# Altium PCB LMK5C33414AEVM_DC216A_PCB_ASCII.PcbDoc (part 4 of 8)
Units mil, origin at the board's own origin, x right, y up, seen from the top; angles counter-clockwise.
Board outline 7000 x 9161 mil, 8 copper layers (L1-Top Layer (GTL), L2-GND Plane (GP1), L3-Mid-Layer 2 (G1), L4-Mid-Layer 3 (G2), L5-Mid-Layer 4 (G3), L6-Mid-Layer 5 (G4), L7-Mid-Layer 6 (G5), L8-Bottom Layer (GBL)), stack 61.2 mil thick; 523 components, 286 nets, 1391 pads, 2227 vias.
Unrouted connection lines stored in the file: 56.
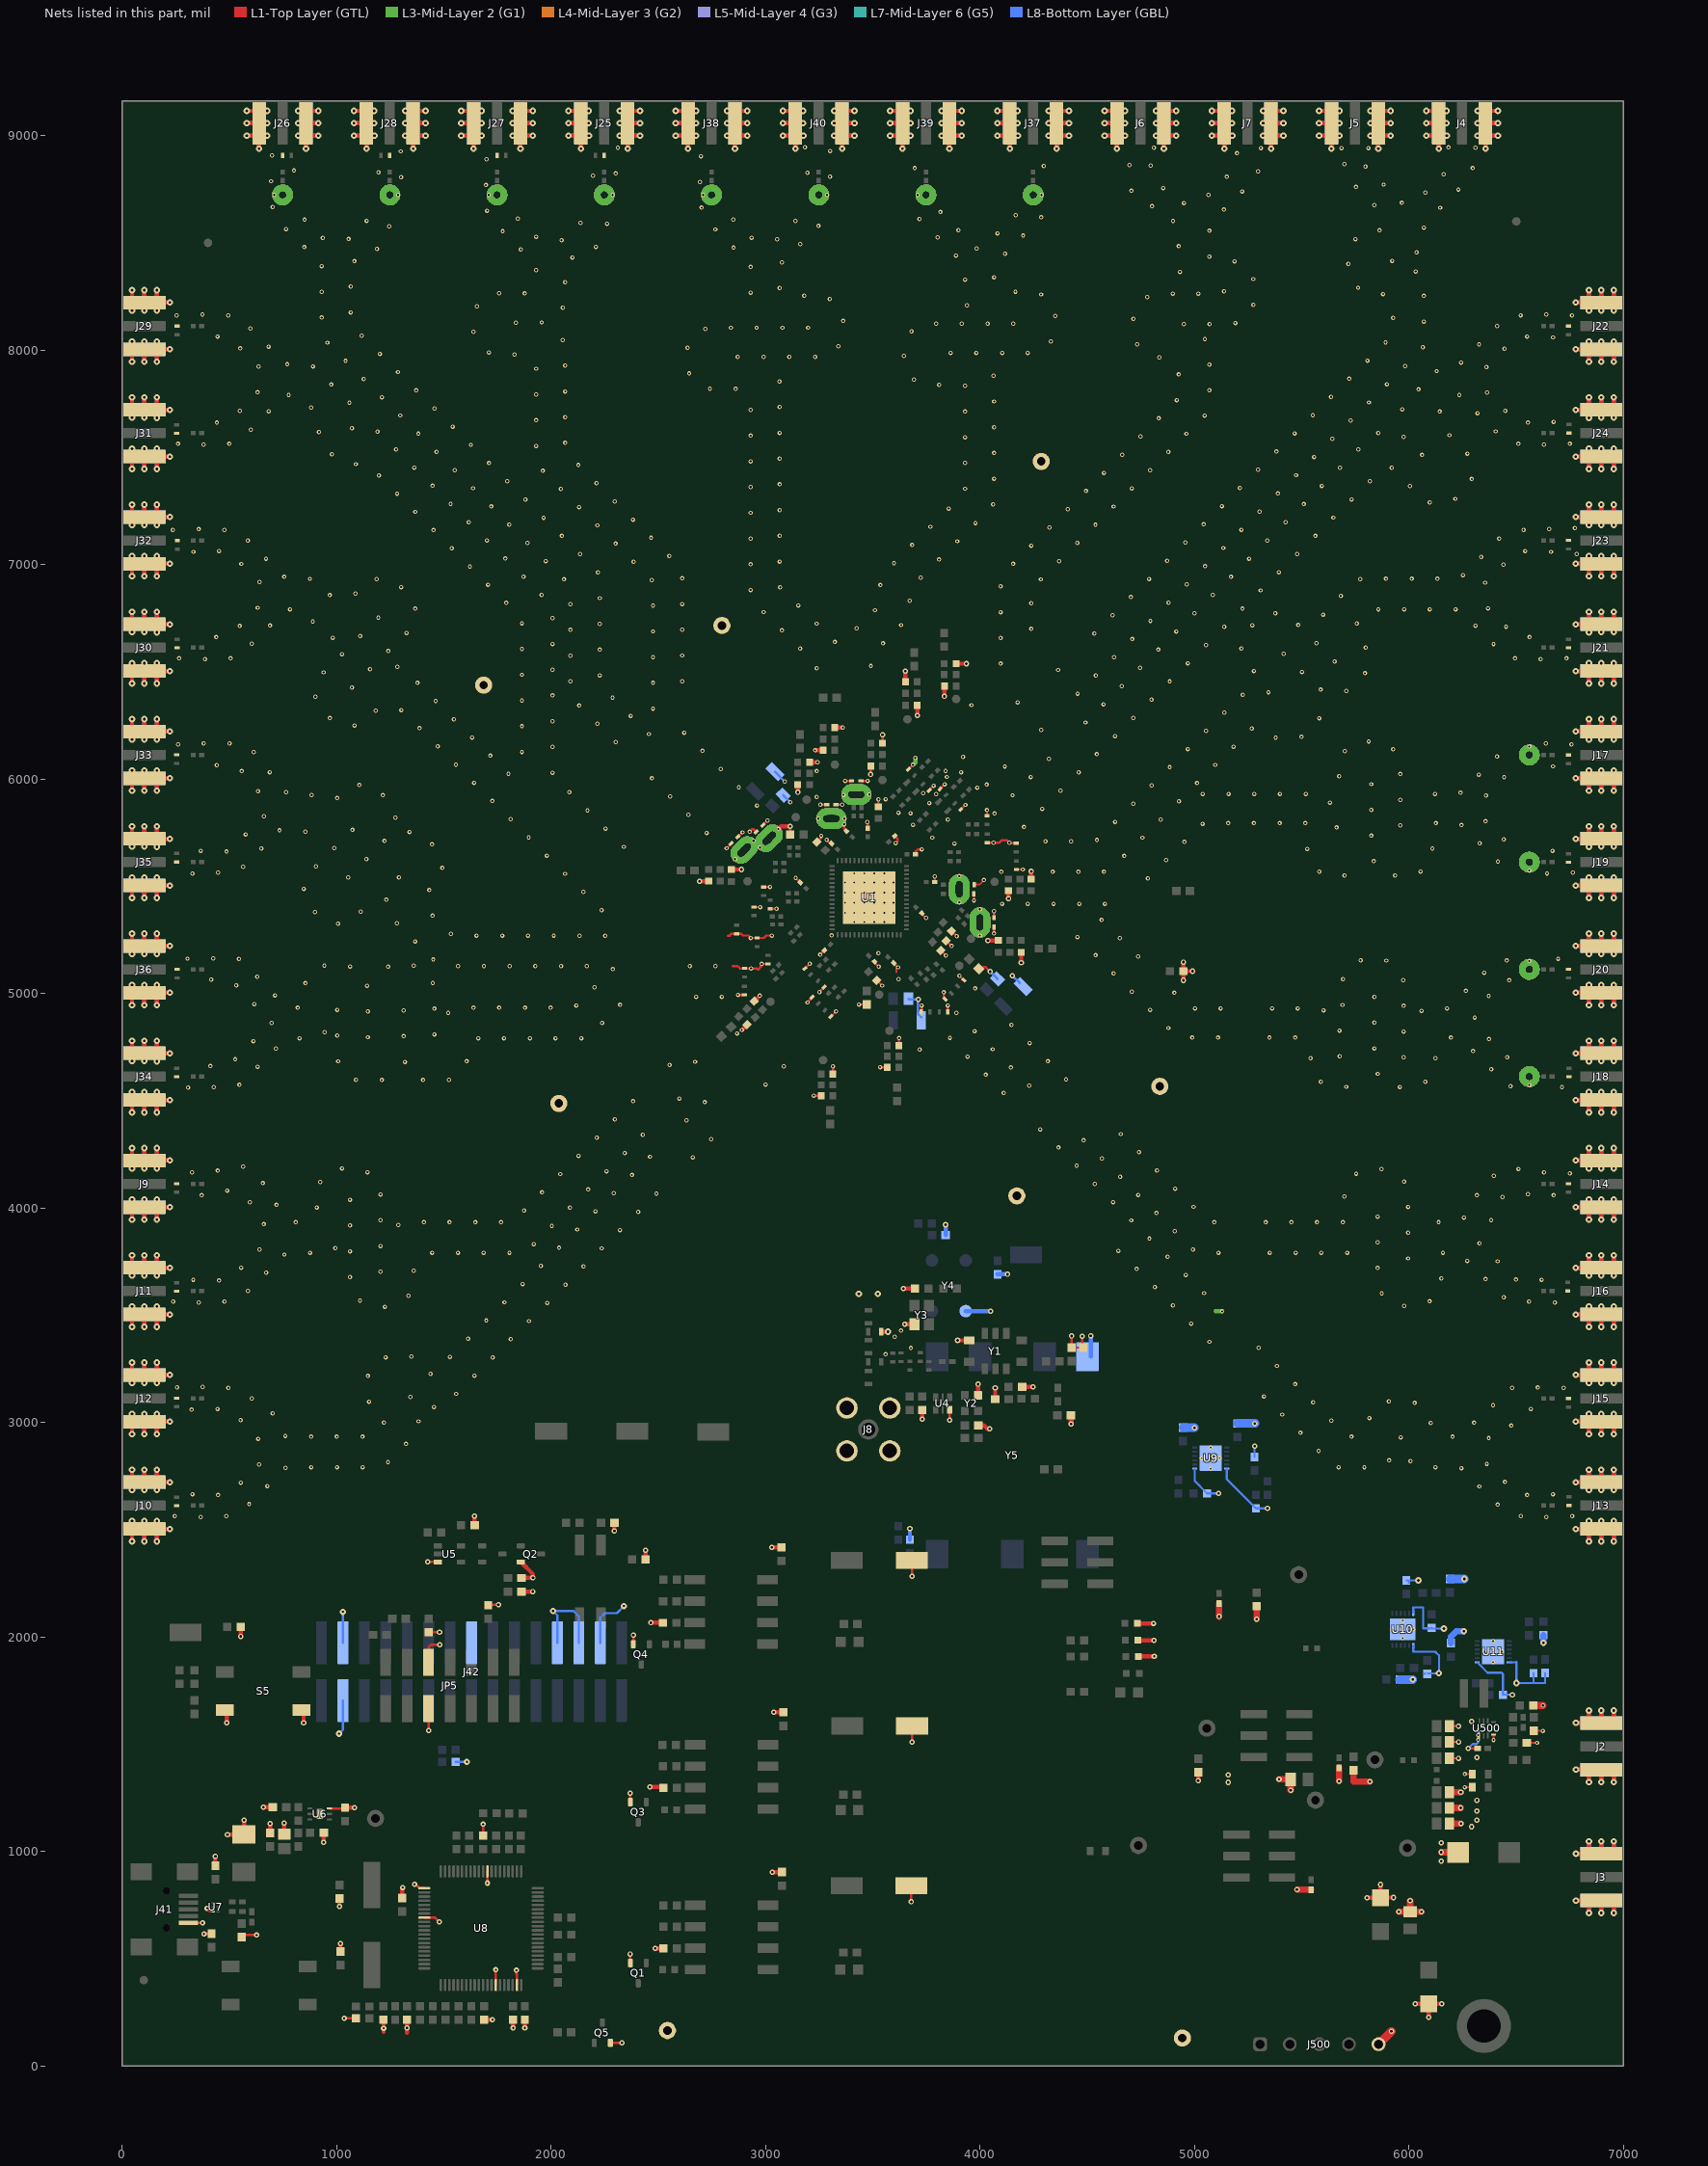
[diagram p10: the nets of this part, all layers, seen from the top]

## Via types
v1: diameter 20, hole 10, L1-Top Layer (GTL) to L8-Bottom Layer (GBL), tented top, 1246 vias
v2: diameter 30, hole 12, L1-Top Layer (GTL) to L8-Bottom Layer (GBL), 519 vias
v3: diameter 25, hole 12, L1-Top Layer (GTL) to L8-Bottom Layer (GBL), tented top, 198 vias
v4: diameter 30, hole 12, L1-Top Layer (GTL) to L8-Bottom Layer (GBL), tented top, 57 vias
v5: diameter 20, hole 10, L1-Top Layer (GTL) to L8-Bottom Layer (GBL), 47 vias
v6: diameter 19.68, hole 7.87, L1-Top Layer (GTL) to L8-Bottom Layer (GBL), 47 vias
v7: diameter 25, hole 10, L1-Top Layer (GTL) to L8-Bottom Layer (GBL), tented top, 35 vias
v8: diameter 25, hole 12, L1-Top Layer (GTL) to L8-Bottom Layer (GBL), 24 vias
v9: diameter 18, hole 10, L1-Top Layer (GTL) to L8-Bottom Layer (GBL), tented top, 12 vias
v10: diameter 40, hole 20, L1-Top Layer (GTL) to L8-Bottom Layer (GBL), 10 vias
v11: diameter 30, hole 10, L1-Top Layer (GTL) to L8-Bottom Layer (GBL), 10 vias
v12: diameter 39.37, hole 19.68, L1-Top Layer (GTL) to L8-Bottom Layer (GBL), tented top, 6 vias
v13: diameter 25, hole 10, L1-Top Layer (GTL) to L8-Bottom Layer (GBL), 5 vias
v14: diameter 23, hole 10, L1-Top Layer (GTL) to L8-Bottom Layer (GBL), tented top, 4 vias
v15: diameter 50, hole 28, L1-Top Layer (GTL) to L8-Bottom Layer (GBL), 4 vias
v16: diameter 20/0/0/0/0/0/20 (per signal layer), hole 10, L1-Top Layer (GTL) to L8-Bottom Layer (GBL), tented top, 2 vias
v17: diameter 25, hole 12, L1-Top Layer (GTL) to L8-Bottom Layer (GBL), tented both sides, 1 vias

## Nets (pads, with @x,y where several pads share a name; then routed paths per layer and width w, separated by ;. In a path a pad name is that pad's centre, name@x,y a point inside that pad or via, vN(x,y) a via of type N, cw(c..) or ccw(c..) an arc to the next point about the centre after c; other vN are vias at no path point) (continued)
GND: C1.2 C2.2 C6.1 C7.2 C8.2 C9.2 C10.2 C13.2 C21.1 C22.2 C23.2 C24.2 C27.2 C28.1 C29.2 C30.1 C31.1 C32.2 C33.1 C34.1 C35.2 C36.1 C37.1 C38.2 C39.1 C40.1 C41.2 C42.1 C43.1 C44.2 C45.1 C46.1 C47.2 C48.1 C49.1 C50.2 C51.1 C52.1 C53.2 C54.1 C55.1 C56.2 C57.1 C58.1 C59.2 C60.1 C61.2 C62.2 C63.2 C64.2 C65.2 C66.2 C67.2 C68.1 C69.2 C72.2 C73.1 C74.2 C75.2 C76.1 C77.2 C78.2 C79.1 C80.2 C81.2 C82.2 C83.2 C84.2 C85.2 C86.2 C87.2 C88.2 C89.1 C90.2 C91.2 C92.2 C93.2 C94.2 C95.2 C96.2 C97.2 C129.1 C130.2 C131.2 C132.1 C133.1 C134.1 C135.2 C136.2 C137.1 C138.1 C139.2 C140.1 C141.1 C142.1 C143.1 C144.1 C154.2 C155.2 C156.2 C500.2 C501.2 C502.2 C503.2 C504.2 C505.1 C506.1 C507.2 C508.2 C509.2 C510.2 C512.2 C513.2 C514.2 C515.2 C516.2 D1.2 D2.2 D3.2 D4.2 D5.2 D11.2 J2.2 J2.3 J2.4 J2.5 J3.2 J3.3 J3.4 J3.5 J4.2 J4.3 J4.4 J4.5 J5.2 J5.3 J5.4 J5.5 J6.2 J6.3 J6.4 J6.5 J7.2 J7.3 J7.4 J7.5 J8.2 J8.3 J8.4 J8.5 J9.2 J9.3 J9.4 J9.5 J10.2 J10.3 J10.4 J10.5 J11.2 J11.3 J11.4 J11.5 J12.2 J12.3 J12.4 J12.5 J13.2 J13.3 J13.4 J13.5 J14.2 J14.3 J14.4 J14.5 J15.2 J15.3 J15.4 J15.5 J16.2 J16.3 J16.4 J16.5 J17.2 J17.3 J17.4 J17.5 J18.2 J18.3 J18.4 J18.5 J19.2 J19.3 J19.4 J19.5 J20.2 J20.3 J20.4 J20.5 J21.2 J21.3 J21.4 J21.5 J22.2 J22.3 J22.4 J22.5 J23.2 J23.3 J23.4 J23.5 J24.2 J24.3 J24.4 J24.5 J25.2 J25.3 J25.4 J25.5 J26.2 J26.3 J26.4 J26.5 J27.2 J27.3 J27.4 J27.5 J28.2 J28.3 J28.4 J28.5 J29.2 J29.3 J29.4 J29.5 J30.2 J30.3 J30.4 J30.5 J31.2 J31.3 J31.4 J31.5 J32.2 J32.3 J32.4 J32.5 J33.2 J33.3 J33.4 J33.5 J34.2 J34.3 J34.4 J34.5 J35.2 J35.3 J35.4 J35.5 J36.2 J36.3 J36.4 J36.5 J37.2 J37.3 J37.4 J37.5 J38.2 J38.3 J38.4 J38.5 J39.2 J39.3 J39.4 J39.5 J40.2 J40.3 J40.4 J40.5 J41.5 J42.4 J42.6 J42.8 J42.16 J42.27 J42.28 J500.5 JP5.A03 JP5.B03 Q1.2 Q2.2 Q3.2 Q4.2 Q5.2 R2.1 R5.1 R9.1 R28.1 R32.1 R35.1 R39.1 R42.1 R45.2 R53.1 R62.1 R65.1 R69.1 R72.1 R78.2 R79.2 R82.2 R85.2 R86.2 R88.2 R90.2 R92.2 R94.2 R96.2 R99.2 R101.2 R103.2 R105.2 R109.2 R111.2 R113.2 R115.2 R117.2 R119.2 R121.2 R122.2 R125.2 R127.2 R129.2 R131.2 R133.2 R134.2 R135.2 R136.2 R138.2 R141.2 R143.2 R148.2 R149.1 R167.2 R168.2 R169.2 R170.2 R171.2 R172.2 R173.2 R174.2 R175.2 R176.2 R177.2 R178.2 R179.2 R180.2 R181.2 R182.2 R183.2 R184.2 R185.2 R186.2 R187.2 R188.2 R189.2 R190.2 R191.2 R204.2 R205.2 R502.1 R504.1 S5.3 S5.4 TP19.1 TP20.1 TP21.1 TP22.1 TP23.1 TP24.1 TP25.1 TP26.1 TP32.1 TP35.1 TP39.1 U1.65 U4.3 U5.3 U6.3 U6.7 U7.3 U8.14 U8.19 U8.49 U8.61 U8.68 U9.6 U9.7 U9.13 U10.6 U10.7 U10.13 U11.6 U11.7 U11.13 U500.4 U500.7 Y1.4 Y2.2 Y3.2 Y4.2 Y5.7 | length 95988.8
  L1-Top Layer (GTL) w10: v7(396,735) 396,730 405.68,720.32 U7.3@424.19,720.32 ; 2824,5269 2830.15,5269 ; 2833,5269 2830.15,5269 ; 2845.66,5127.3 2870.34,5127.3 2880.21,5117.43 ; R188.2@2944.73,5402.71 v1(2974.27,5402.71) ; v1(2981.18,5138) R191.2@3010.72,5138 ; R185.2@2991.21,5497 v1(3020.75,5497) ; R187.2@3021,5395 v1(3050.54,5395) ; v1(3029,5270) 3003,5270 2992,5259 R189.2@2960,5259 v1(2930.46,5259) 2919.46,5270 2894,5270 2886,5278 2839.15,5278 2830.15,5269 ; v1(3139.94,5538.93) C51.1@3161.14,5517.73 ; R167.2@3182.16,5116.54 3182.75,5116.54 3205.01,5138.8 v1(3205.6,5138.8) ; v1(3195.85,4958.13) 3195.85,4960.03 3216.56,4980.74 R170.2@3216.56,4982.64 ; C66.2@3239.25,5706.73 3259.02,5726.49 v1(3259.02,5735.31) ; v1(3250.5,5006.5) 3250.5,5007.11 3272.74,5029.35 R169.2@3272.74,5029.96 ; v1(3254.4,5181.04) C33.1@3274.58,5201.22 ; v1(3284.21,5716.79) C60.1@3304.25,5696.75 ; R168.2@3304.24,4893.56 3304.9,4893.56 3327.64,4916.3 v1(3328.3,4916.3) ; v1(3365.75,5789.01) 3365.75,5767.99 C57.1@3376.83,5756.91 ; v1(3435,4948.92) C67.2@3471.84,4948.92 ; v1(3474.04,5799.47) 3476.04,5797.47 C42.1@3476.04,5770.83 ; C48.1@3506.18,5146.28 v1(3527.04,5125.42) ; C62.2@3518.08,5061.96 v1(3543.34,5036.7) ; C39.1@3597.4,5142.27 v1@3616.66,5123.01 ; 3610,5101 3610,5114.35 v1(3617.66,5122.01) ; C54.1@3727,5373.31 3747.89,5352.42 v1(3747.89,5352.18) ; C45.1@3788.61,5519.89 v1(3788.61,5546.18) ; C65.2@3816.71,5201.07 v1(3840.61,5177.17) ; v3(3857.53,3011) U4.3@3857.53,3059.17 ; v1(3971.41,5434.16) R204.2@3971.41,5463.49 ; R176.2@3972,5508 3997,5508 v1(4018,5529) ; R178.2@4032,5829 v5(4032,5855) ; v1(4136.82,5702.51) 4138.64,5700.69 R205.2@4168,5700.69 ; R179.2@4169,5578.31 v1(4199.02,5578.31) ; C80.2@4426.24,3349.13 C80.2@4426.24,3349.38 ; v3(4426.24,3403.18) C80.2@4426.24,3349.38 ; C79.1@4475.99,3349.38 v3(4475.99,3402.56) ; C79.1@4480.99,3349.38 C80.2@4426.24,3349.38 ; C501.2@6185.33,1584.4 v8(6230.3,1584.4) ; C503.2@6188.03,1434.1 v8(6230.3,1434.1) ; C502.2@6188.03,1510.6 v8(6230.7,1510.6) ; v5(6259.4,1299.4) C506.1@6295.38,1299.4 ; v5(6259.8,1360.5) C505.1@6295.38,1360.5 ; v8@6276.5,1480.3 C507.2@6320.68,1480.3 ; v5(6322.1,1520.3) v5(6322.1,1542.3) ; v5(6393.92,1519.22) U500.7@6393.92,1544.47 ; C512.2@6549.1,1506.3 v5(6596.7,1506.3) ; R504.1@6581.9,1561.9 v5(6623.8,1561.9)
  L1-Top Layer (GTL) w11: 577.5,610 v7(626,610) ; U6.3@965.78,1200.18 1034.67,1200.18 C130.2@1039,1204.51 ; v7(1034.71,221.85) C139.2@1089.72,221.85 ; v3(1424.5,2349.5) U5.3@1471.28,2349.5 ; v3(1428.36,1563.6) JP5.A03@1428.36,1665.92 ; JP5.B03@1428.36,1880.88 1428.36,1952.36 1439,1963 v3(1480,1963) ; C92.2@1429.04,2022.18 v3(1479.28,2022.18) ; C93.2@1706,2150.43 v3(1753.79,2150.43) ; Q5.2@2275.8,107.08 v3(2329.92,107.08) ; Q1.2@2368.68,479.73 v3(2368.68,521.67) ; Q3.2@2368.69,1230.06 v3(2368.69,1272) ; Q4.2@2382.91,1966.04 v3(2382.91,2007.98) ; v1(2818.13,5677.07) R182.2@2839.69,5698.63 ; v1(2870.58,4993.86) R190.2@2901.07,4993.86 ; R184.2@2870.81,5729.74 v1(2892.37,5751.3) ; 2880.21,5117.43 R134.2@2901.71,5117.43 v1(2932.2,5117.43) 2958.89,5117.43 2964.64,5111.68 2981.18,5128.22 v1(2981.18,5138) ; v1(2924.96,5753.88) 2936.47,5765.4 2943.93,5765.4 R183.2@2955.45,5753.88 ; R181.2@2986.56,5785 v1(3008.12,5806.56) ; C75.2@3114.27,5741.54 v3(3114.27,5779.72) ; v1(3224.72,4524.1) C37.1@3258.53,4524.1 ; v1(3255.04,5880.05) R138.2@3284.39,5880.05 ; C38.2@3313.65,4623.46 v1(3313.65,4660.6) ; R143.2@3328.39,5880.2 v1(3356.88,5880.2) ; v1(3370.1,5991.63) R141.2@3400.59,5991.63 ; R136.2@3444.59,5991.63 v1(3475.08,5991.63) ; v3(3489.58,6021.24) C41.2@3489.58,6060.78 ; C61.2@3526.25,5871.25 v1(3526.25,5905.61) ; v1(3533.67,4656.73) C46.1@3566.8,4656.73 ; C40.1@3544.7,6166.96 v3(3544.7,6205.89) ; C36.1@3601.6,5734.83 3614.61,5721.82 3614.61,5709.51 v1(3606.81,5701.7) ; C47.2@3621.92,4756.58 v1(3621.92,4792.04) ; R35.1@3665.53,6044.9 v1(3687.09,6066.46) ; v3(3679,765) TP32.1@3679,840 ; v3(3682,2282) TP39.1@3682,2357 ; v3(3683,1510) TP35.1@3683,1585 ; C30.1@3699.03,5649.19 3699.03,5661.59 3709.24,5671.81 v1@3728.03,5671.81 ; R171.2@3727.02,4914.81 v1(3727.02,4944.19) ; R39.1@3761.75,5947.25 v1(3783.31,5968.81) ; R32.1@3813.05,5953.9 v1(3834.61,5975.46) ; v1(3830.4,5005.51) 3830.4,4979.46 R174.2@3836.8,4973.06 ; C64.2@3841.84,5246.38 v1(3866.95,5221.26) ; R173.2@3849.55,4914.64 v1(3849.55,4944.02) ; C63.2@3866.97,5291.68 v1(3891.19,5267.46) ; v1(3903.68,5082.9) R172.2@3924.05,5062.53 ; R28.1@3909.77,5857.94 v1(3931.33,5879.5) ; 4014.19,5123.38 4025.9,5123.38 v3(4047.22,5102.07) ; R180.2@4034,5703 v1(4063,5702.63) 4088.63,5702.63 4101,5715 4124.33,5715 v1(4136.82,5702.51) ; v1(4064.49,5279.75) R175.2@4064.49,5309.45 ; R177.2@4064.82,5353.81 v1(4064.82,5383.51)
  L1-Top Layer (GTL) w12: J41.5@308.36,667.01 v7(373.99,667.01) ; v7(381,615) 382.5,616.5 R148.2@416,616.5 ; v7@1367.71,846.85 1385.7,828.86 U8.61@1407.95,828.86 ; U8.68@1407.95,691.06 1458.5,691.06 v7(1477.71,671.85) ; C144.1@1682.71,1073.35 v7(1682.71,1126.85) ; U8.49@1702.24,906.61 v7(1702.24,852.32) v7@1702.71,851.85 ; U8.14@1741.61,377.09 v7@1741.61,448 ; v7(1838,446) 1838,426.56 1840.03,424.53 U8.19@1840.03,377.09
  L1-Top Layer (GTL) w20: v2(45.56,2445.57) J10.2@45.56,2503.44 ; v2@45.56,2542.7 J10.2@45.56,2503.44 ; v2@45.56,2682.3 J10.3@45.56,2721.56 ; v2(45.56,2779.43) J10.3@45.56,2721.56 ; v2(45.56,2945.57) J12.2@45.56,3003.44 ; v2@45.56,3042.7 J12.2@45.56,3003.44 ; v2@45.56,3182.3 J12.3@45.56,3221.56 ; v2(45.56,3279.43) J12.3@45.56,3221.56 ; v2(45.56,3445.57) J11.2@45.56,3503.44 ; v2@45.56,3542.7 J11.2@45.56,3503.44 ; v2@45.56,3682.3 J11.3@45.56,3721.56 ; v2(45.56,3779.43) J11.3@45.56,3721.56 ; v2(45.56,3945.57) J9.2@45.56,4003.44 ; v2@45.56,4042.7 J9.2@45.56,4003.44 ; v2@45.56,4182.3 J9.3@45.56,4221.56 ; v2(45.56,4279.43) J9.3@45.56,4221.56 ; v2(45.56,4445.57) J34.2@45.56,4503.44 ; v2@45.56,4542.7 J34.2@45.56,4503.44 ; v2@45.56,4682.3 J34.3@45.56,4721.56 ; v2(45.56,4779.43) J34.3@45.56,4721.56 ; v2(45.56,4945.57) J36.2@45.56,5003.44 ; v2@45.56,5042.7 J36.2@45.56,5003.44 ; v2@45.56,5182.3 J36.3@45.56,5221.56 ; v2(45.56,5279.43) J36.3@45.56,5221.56 ; v2(45.56,5445.57) J35.2@45.56,5503.44 ; v2@45.56,5542.7 J35.2@45.56,5503.44 ; v2@45.56,5682.3 J35.3@45.56,5721.56 ; v2(45.56,5779.43) J35.3@45.56,5721.56 ; v2(45.56,5945.57) J33.2@45.56,6003.44 ; v2@45.56,6042.7 J33.2@45.56,6003.44 ; v2@45.56,6182.3 J33.3@45.56,6221.56 ; v2(45.56,6279.43) J33.3@45.56,6221.56 ; v2(45.56,6445.57) J30.2@45.56,6503.44 ; v2@45.56,6542.7 J30.2@45.56,6503.44 ; v2@45.56,6682.3 J30.3@45.56,6721.56 ; v2(45.56,6779.43) J30.3@45.56,6721.56 ; v2(45.56,6945.57) J32.2@45.56,7003.44 ; v2@45.56,7042.7 J32.2@45.56,7003.44 ; v2@45.56,7182.3 J32.3@45.56,7221.56 ; v2(45.56,7279.43) J32.3@45.56,7221.56 ; v2(45.56,7445.57) J31.2@45.56,7503.44 ; v2@45.56,7542.7 J31.2@45.56,7503.44 ; v2@45.56,7682.3 J31.3@45.56,7721.56 ; v2(45.56,7779.43) J31.3@45.56,7721.56 ; v2(45.56,7945.57) J29.2@45.56,8003.44 ; v2@45.56,8042.7 J29.2@45.56,8003.44 ; v2@45.56,8182.3 J29.3@45.56,8221.56 ; v2(45.56,8279.43) J29.3@45.56,8221.56 ; v2(103.43,2445.57) J10.2@103.43,2503.44 ; v2@103.43,2542.7 J10.2@103.43,2503.44 ; v2@103.43,2682.3 J10.3@103.43,2721.56 ; v2(103.43,2779.43) J10.3@103.43,2721.56 ; v2(103.43,2945.57) J12.2@103.43,3003.44 ; v2@103.43,3042.7 J12.2@103.43,3003.44 ; v2@103.43,3182.3 J12.3@103.43,3221.56 ; v2(103.43,3279.43) J12.3@103.43,3221.56 ; v2(103.43,3445.57) J11.2@103.43,3503.44 ; v2@103.43,3542.7 J11.2@103.43,3503.44 ; v2@103.43,3682.3 J11.3@103.43,3721.56 ; v2(103.43,3779.43) J11.3@103.43,3721.56 ; v2(103.43,3945.57) J9.2@103.43,4003.44 ; v2@103.43,4042.7 J9.2@103.43,4003.44 ; v2@103.43,4182.3 J9.3@103.43,4221.56 ; v2(103.43,4279.43) J9.3@103.43,4221.56 ; v2(103.43,4445.57) J34.2@103.43,4503.44 ; v2@103.43,4542.7 J34.2@103.43,4503.44 ; v2@103.43,4682.3 J34.3@103.43,4721.56 ; v2(103.43,4779.43) J34.3@103.43,4721.56 ; v2(103.43,4945.57) J36.2@103.43,5003.44 ; v2@103.43,5042.7 J36.2@103.43,5003.44 ; v2@103.43,5182.3 J36.3@103.43,5221.56 ; v2(103.43,5279.43) J36.3@103.43,5221.56 ; v2(103.43,5445.57) J35.2@103.43,5503.44 ; v2@103.43,5542.7 J35.2@103.43,5503.44 ; v2@103.43,5682.3 J35.3@103.43,5721.56 ; v2(103.43,5779.43) J35.3@103.43,5721.56 ; v2(103.43,5945.57) J33.2@103.43,6003.44 ; v2@103.43,6042.7 J33.2@103.43,6003.44 ; v2@103.43,6182.3 J33.3@103.43,6221.56 ; v2(103.43,6279.43) J33.3@103.43,6221.56 ; v2(103.43,6445.57) J30.2@103.43,6503.44 ; v2@103.43,6542.7 J30.2@103.43,6503.44 ; v2@103.43,6682.3 J30.3@103.43,6721.56 ; v2(103.43,6779.43) J30.3@103.43,6721.56 ; v2(103.43,6945.57) J32.2@103.43,7003.44 ; v2@103.43,7042.7 J32.2@103.43,7003.44 ; v2@103.43,7182.3 J32.3@103.43,7221.56 ; v2(103.43,7279.43) J32.3@103.43,7221.56 ; v2(103.43,7445.57) J31.2@103.43,7503.44 ; v2@103.43,7542.7 J31.2@103.43,7503.44 ; v2@103.43,7682.3 J31.3@103.43,7721.56 ; v2(103.43,7779.43) J31.3@103.43,7721.56 ; v2(103.43,7945.57) J29.2@103.43,8003.44 ; v2@103.43,8042.7 J29.2@103.43,8003.44 ; v2@103.43,8182.3 J29.3@103.43,8221.56 ; v2(103.43,8279.43) J29.3@103.43,8221.56 ; v2@161,2543 161,2503.74 J10.2@161.3,2503.44 ; v2@161,2682 161,2721.26 J10.3@161.3,2721.56 ; v2@161,3043 161,3003.74 J12.2@161.3,3003.44 ; v2@161,3182 161,3221.26 J12.3@161.3,3221.56 ; v2@161,3543 161,3503.74 J11.2@161.3,3503.44 ; v2@161,3682 161,3721.26 J11.3@161.3,3721.56 ; v2@161,4043 161,4003.74 J9.2@161.3,4003.44 ; v2@161,4182 161,4221.26 J9.3@161.3,4221.56 ; v2@161,4543 161,4503.74 J34.2@161.3,4503.44 ; v2@161,4682 161,4721.26 J34.3@161.3,4721.56 ; v2@161,5043 161,5003.74 J36.2@161.3,5003.44 ; v2@161,5182 161,5221.26 J36.3@161.3,5221.56 ; v2@161,5543 161,5503.74 J35.2@161.3,5503.44 ; v2@161,5682 161,5721.26 J35.3@161.3,5721.56 ; v2@161,6043 161,6003.74 J33.2@161.3,6003.44 ; v2@161,6182 161,6221.26 J33.3@161.3,6221.56 ; v2@161,6543 161,6503.74 J30.2@161.3,6503.44 ; v2@161,6682 161,6721.26 J30.3@161.3,6721.56 ; v2@161,7043 161,7003.74 J32.2@161.3,7003.44 ; v2@161,7182 161,7221.26 J32.3@161.3,7221.56 ; v2@161,7543 161,7503.74 J31.2@161.3,7503.44 ; v2@161,7682 161,7721.26 J31.3@161.3,7721.56 ; v2@161,8043 161,8003.74 J29.2@161.3,8003.44 ; v2@161,8182 161,8221.26 J29.3@161.3,8221.56 ; v2(161.3,2445.57) J10.2@161.3,2503.44 ; v2(161.3,2779.43) J10.3@161.3,2721.56 ; v2(161.3,2945.57) J12.2@161.3,3003.44 ; v2(161.3,3279.43) J12.3@161.3,3221.56 ; v2(161.3,3445.57) J11.2@161.3,3503.44 ; v2(161.3,3779.43) J11.3@161.3,3721.56 ; v2(161.3,3945.57) J9.2@161.3,4003.44 ; v2(161.3,4279.43) J9.3@161.3,4221.56 ; v2(161.3,4445.57) J34.2@161.3,4503.44 ; v2(161.3,4779.43) J34.3@161.3,4721.56 ; v2(161.3,4945.57) J36.2@161.3,5003.44 ; v2(161.3,5279.43) J36.3@161.3,5221.56 ; v2(161.3,5445.57) J35.2@161.3,5503.44 ; v2(161.3,5779.43) J35.3@161.3,5721.56 ; v2(161.3,5945.57) J33.2@161.3,6003.44 ; v2(161.3,6279.43) J33.3@161.3,6221.56 ; v2(161.3,6445.57) J30.2@161.3,6503.44 ; v2(161.3,6779.43) J30.3@161.3,6721.56 ; v2(161.3,6945.57) J32.2@161.3,7003.44 ; v2(161.3,7279.43) J32.3@161.3,7221.56 ; v2(161.3,7445.57) J31.2@161.3,7503.44 ; v2(161.3,7779.43) J31.3@161.3,7721.56 ; v2(161.3,7945.57) J29.2@161.3,8003.44 ; v2(161.3,8279.43) J29.3@161.3,8221.56 ; J10.2@163.5,2503.44 v2(221.37,2503.44) ; J10.3@163.5,2721.56 v2(221.37,2721.56) ; J12.2@163.5,3003.44 v2(221.37,3003.44) ; J12.3@163.5,3221.56 v2(221.37,3221.56) ; J11.2@163.5,3503.44 v2(221.37,3503.44) ; J11.3@163.5,3721.56 v2(221.37,3721.56) ; J9.2@163.5,4003.44 v2(221.37,4003.44) ; J9.3@163.5,4221.56 v2(221.37,4221.56) ; J34.2@163.5,4503.44 v2(221.37,4503.44) ; J34.3@163.5,4721.56 v2(221.37,4721.56) ; J36.2@163.5,5003.44 v2(221.37,5003.44) ; J36.3@163.5,5221.56 v2(221.37,5221.56) ; J35.2@163.5,5503.44 v2(221.37,5503.44) ; J35.3@163.5,5721.56 v2(221.37,5721.56) ; J33.2@163.5,6003.44 v2(221.37,6003.44) ; J33.3@163.5,6221.56 v2(221.37,6221.56) ; J30.2@163.5,6503.44 v2(221.37,6503.44) ; J30.3@163.5,6721.56 v2(221.37,6721.56) ; J32.2@163.5,7003.44 v2(221.37,7003.44) ; J32.3@163.5,7221.56 v2(221.37,7221.56) ; J31.2@163.5,7503.44 v2(221.37,7503.44) ; J31.3@163.5,7721.56 v2(221.37,7721.56) ; J29.2@163.5,8003.44 v4(221.37,8003.44) ; J29.3@163.5,8221.56 v2(221.37,8221.56) ; C133.1@434.1,933.29 v3(434.1,977.79) ; S5.3@477.76,1659.56 487.29,1650.02 v3(487.29,1600.29) v3@487.29,1597.79 ; v3@486.89,1597.79 v3@486.89,1598.19 ; v3(490.66,1078.66) D11.2@567.86,1078.66 v3(567.86,1145.86) ; v3(552.66,2002.75) C96.2@552.66,2047.25 ; v2(580.57,8999.7) J26.2@638.44,8999.7 ; v2(580.57,9057.57) J26.2@638.44,9057.57 ; v2(580.57,9115.44) J26.2@638.44,9115.44 ; v2(638.44,8939.63) J26.2@638.44,8997.5 ; v3(657.75,1207) C132.1@701.5,1207 ; v2@677.7,9057.57 J26.2@638.44,9057.57 ; v2@677.7,9115.44 J26.2@638.44,9115.44 ; v2@678,9000 638.74,9000 J26.2@638.44,8999.7 ; C134.1@689.47,1085.72 v3(689.47,1129.47) ; C131.2@755.13,1079.94 v3(755.13,1131.87) ; v2@817,9000 856.26,9000 J26.3@856.56,8999.7 ; v2@817.3,9057.57 J26.3@856.56,9057.57 ; v2@817.3,9115.44 J26.3@856.56,9115.44 ; S5.4@836.02,1659.56 845.56,1650.02 845.56,1603.6 v3@848.47,1600.69 ; v2(856.56,8939.63) J26.3@856.56,8997.5 ; v2(914.43,8999.7) J26.3@856.56,8999.7 ; v2(914.43,9057.57) J26.3@856.56,9057.57 ; v2(914.43,9115.44) J26.3@856.56,9115.44 ; v3(939.46,1042.87) C129.1@939.46,1086.62 ; v7(1012.71,743) C135.2@1012.71,780.35 ; C136.2@1017.71,533.35 v7(1017.71,570.7) ; C130.2@1039,1204.51 v3(1082.75,1204.51) ; v2(1080.57,8999.7) J28.2@1138.44,8999.7 ; v2(1080.57,9057.57) J28.2@1138.44,9057.57 ; v2(1080.57,9115.44) J28.2@1138.44,9115.44 ; v2(1138.44,8939.63) J28.2@1138.44,8997.5 ; v2@1177.7,9057.57 J28.2@1138.44,9057.57 ; v2@1177.7,9115.44 J28.2@1138.44,9115.44 ; v2@1178,9000 1138.74,9000 J28.2@1138.44,8999.7 ; C137.1@1217.71,213.35 C137.1@1218.71,214.35 ; C137.1@1217.71,215.35 C137.1@1218.71,214.35 ; 1218.71,158 C137.1@1218.71,214.35 ; C140.1@1305.71,782.35 1305.71,829.85 v7(1307.71,831.85) ; v2@1317,9000 1356.26,9000 J28.3@1356.56,8999.7 ; v2@1317.3,9057.57 J28.3@1356.56,9057.57 ; v2@1317.3,9115.44 J28.3@1356.56,9115.44 ; C138.1@1326.71,214.35 C138.1@1327.71,215.35 1327.71,155 ; v2(1356.56,8939.63) J28.3@1356.56,8997.5 ; v2(1414.43,8999.7) J28.3@1356.56,8999.7 ; v2(1414.43,9057.57) J28.3@1356.56,9057.57 ; v2(1414.43,9115.44) J28.3@1356.56,9115.44 ; v2(1580.57,8999.7) J27.2@1638.44,8999.7 ; v2(1580.57,9057.57) J27.2@1638.44,9057.57 ; v2(1580.57,9115.44) J27.2@1638.44,9115.44 ; v2(1638.44,8939.63) J27.2@1638.44,8997.5 ; C89.1@1642.82,2520.22 v3(1642.82,2564.18) ; v2@1677.7,9057.57 J27.2@1638.44,9057.57 ; v2@1677.7,9115.44 J27.2@1638.44,9115.44 ; v2@1678,9000 1638.74,9000 J27.2@1638.44,8999.7 ; C142.1@1687.71,215.35 v7(1726.29,215.35) ; v2@1817,9000 1856.26,9000 J27.3@1856.56,8999.7 ; v2@1817.3,9057.57 J27.3@1856.56,9057.57 ; v2@1817.3,9115.44 J27.3@1856.56,9115.44 ; v7(1822.71,176.77) C143.1@1822.71,215.35 ; v2(1856.56,8939.63) J27.3@1856.56,8997.5 ; Q2.2@1858.17,2349.5 1915.05,2292.61 v3(1915.05,2276.57) 1862.4,2276.57 C90.2@1862.03,2276.2 ; R62.1@1862.03,2211.2 1862.4,2211.57 v3(1914.05,2211.56) ; v7(1877.05,176.77) C141.1@1877.05,215.35 ; v2(1914.43,8999.7) J27.3@1856.56,8999.7 ; v2(1914.43,9057.57) J27.3@1856.56,9057.57 ; v2(1914.43,9115.44) J27.3@1856.56,9115.44 ; v2(2080.57,8999.7) 2138.44,8999.7 J25.2@2138.44,9057.57 ; v2(2080.57,9057.57) J25.2@2138.44,9057.57 ; v2(2080.57,9115.44) J25.2@2138.44,9115.44 ; v2(2138.44,8939.63) J25.2@2138.44,8997.5 ; J25.2@2138.74,9000 v2@2178,9000 ; v2@2177.7,9057.57 J25.2@2138.44,9057.57 ; v2@2177.7,9115.44 J25.2@2138.44,9115.44 ; v3(2294.75,2493.21) R69.1@2294.75,2531.71 ; v2@2317,9000 2356.26,9000 J25.3@2356.56,8999.7 ; v2@2317.3,9057.57 J25.3@2356.56,9057.57 ; v2@2317.3,9115.44 J25.3@2356.56,9115.44 ; v2(2356.56,8939.63) J25.3@2356.56,8997.5 ; v2(2414.43,8999.7) J25.3@2356.56,8999.7 ; v2(2414.43,9057.57) J25.3@2356.56,9057.57 ; v2(2414.43,9115.44) J25.3@2356.56,9115.44 ; C94.2@2440.5,2361 v3(2440.5,2403.45) ; v3(2460.55,1300.6) 2517.99,1300.6 R65.1@2522.76,1295.82 ; v3(2464,2066) R72.1@2521.21,2066.05 ; v3(2485.01,548.55) R53.1@2523.52,548.55 ; v2(2580.57,8999.7) 2638.44,8999.7 J38.2@2638.44,9057.57 ; v2(2580.57,9057.57) J38.2@2638.44,9057.57 ; v2(2580.57,9115.44) J38.2@2638.44,9115.44 ; v2(2638.44,8939.63) J38.2@2638.44,8997.5 ; J38.2@2638.74,9000 v2@2678,9000 ; v2@2677.7,9057.57 J38.2@2638.44,9057.57 ; v2@2677.7,9115.44 J38.2@2638.44,9115.44 ; v3(2691.93,5523.49) C49.1@2734.38,5523.49 ; v2@2817,9000 2856.26,9000 J38.3@2856.56,8999.7 ; v2@2817.3,9057.57 J38.3@2856.56,9057.57 ; v2@2817.3,9115.44 J38.3@2856.56,9115.44 ; C50.2@2840.69,5578.3 v3(2887.76,5578.3) ; v2(2856.56,8939.63) J38.3@2856.56,8997.5 ; v1(2888.9,4830.02) C31.1@2913.03,4854.15 ; v2(2914.43,8999.7) J38.3@2856.56,8999.7 ; v2(2914.43,9057.57) J38.3@2856.56,9057.57 ; v2(2914.43,9115.44) J38.3@2856.56,9115.44 ; C32.2@2946.81,4963.91 v1(2972.59,4989.69) ; v3(3029.5,2417.5) C95.2@3074,2417.5 ; v3(3031.5,903.5) C88.2@3076,903.5 ; v3(3038.5,1648.5) C91.2@3083,1648.5 ; v1(3059.48,5767.23) 3071.97,5779.72 v3(3114.27,5779.72) ; v2(3080.57,8999.7) 3138.44,8999.7 J40.2@3138.44,9057.57 ; v2(3080.57,9057.57) J40.2@3138.44,9057.57 ; v2(3080.57,9115.44) J40.2@3138.44,9115.44 ; v2(3138.44,8939.63) J40.2@3138.44,8997.5 ; J40.2@3138.74,9000 v2@3178,9000 ; v3(3149.57,5938.03) C59.2@3149.57,5973.89 ; v2@3177.7,9057.57 J40.2@3138.44,9057.57 ; v2@3177.7,9115.44 J40.2@3138.44,9115.44 ; C58.1@3204.69,6077.89 v1(3241.92,6077.89) ; v1(3230.15,6133.77) C56.2@3267.38,6133.77 ; v2@3317,9000 3356.26,9000 J40.3@3356.56,8999.7 ; v2@3317.3,9057.57 J40.3@3356.56,9057.57 ; v2@3317.3,9115.44 J40.3@3356.56,9115.44 ; C55.1@3322.5,6239.95 v1(3359.73,6239.95) ; v2(3356.56,8939.63) J40.3@3356.56,8997.5 ; v2(3414.43,8999.7) J40.3@3356.56,8999.7 ; v2(3414.43,9057.57) J40.3@3356.56,9057.57 ; v2(3414.43,9115.44) J40.3@3356.56,9115.44 ; R42.1@3539,3423 v4(3570.1,3423) ; v2(3580.57,8999.7) 3638.44,8999.7 J39.2@3638.44,9057.57 ; v2(3580.57,9057.57) J39.2@3638.44,9057.57 ; v2(3580.57,9115.44) J39.2@3638.44,9115.44 ; v2(3638.44,8939.63) J39.2@3638.44,8997.5 ; J39.2@3638.74,9000 v2@3678,9000 ; v3(3642.84,3624.84) C83.2@3696.14,3624.84 ; v7(3648.46,3457.73) Y3.2@3693.86,3457.73 ; C34.1@3651,6453 v3(3651,6503.45) ; v2@3677.7,9057.57 J39.2@3638.44,9057.57 ; v2@3677.7,9115.44 J39.2@3638.44,9115.44 ; v3(3706.73,6295.69) C35.2@3706.73,6344.14 ; v3(3729.54,3015.46) C87.2@3729.54,3058.21 ; v2@3817,9000 3856.26,9000 J39.3@3856.56,8999.7 ; v2@3817.3,9057.57 J39.3@3856.56,9057.57 ; v2@3817.3,9115.44 J39.3@3856.56,9115.44 ; v3(3833.61,6385.22) C29.2@3833.61,6433.67 ; v2(3856.56,8939.63) J39.3@3856.56,8997.5 ; C28.1@3887.39,6537.74 v3(3935.84,6537.74) ; v3(3894.97,3382.66) Y1.4@3946.72,3382.66 ; v2(3914.43,8999.7) J39.3@3856.56,8999.7 ; v2(3914.43,9057.57) J39.3@3856.56,9057.57 ; v2(3914.43,9115.44) J39.3@3856.56,9115.44 ; Y2.2@3989.9,3126.73 v3(3989.9,3178.48) ; C82.2@3991.36,2985.56 4018.44,2985.56 4034,2970 v3(4045,2970) ; v3(4036.32,5247.23) C53.2@4084.77,5247.23 ; R45.2@4070.43,3108.93 v3(4070.43,3160.68) ; v2(4080.57,8999.7) 4138.44,8999.7 J37.2@4138.44,9057.57 ; v2(4080.57,9057.57) J37.2@4138.44,9057.57 ; v2(4080.57,9115.44) J37.2@4138.44,9115.44 ; v3(4133,5443.04) C44.2@4133,5478.47 ; v2(4138.44,8939.63) J37.2@4138.44,8997.5 ; J37.2@4138.74,9000 v2@4178,9000 ; v2@4177.7,9057.57 J37.2@4138.44,9057.57 ; v2@4177.7,9115.44 J37.2@4138.44,9115.44 ; v3(4191.67,5143.65) C52.1@4191.67,5192.11 ; C81.2@4195.69,3166.46 v3(4247.44,3166.46) ; C43.1@4238.63,5533.59 v3(4238.63,5569.45) ; v2@4317,9000 4356.26,9000 J37.3@4356.56,8999.7 ; v2@4317.3,9057.57 J37.3@4356.56,9057.57 ; v2@4317.3,9115.44 J37.3@4356.56,9115.44 ; v2(4356.56,8939.63) J37.3@4356.56,8997.5 ; v2(4414.43,8999.7) J37.3@4356.56,8999.7 ; v2(4414.43,9057.57) J37.3@4356.56,9057.57 ; v2(4414.43,9115.44) J37.3@4356.56,9115.44 ; v2(4580.57,8999.7) 4638.44,8999.7 J6.2@4638.44,9057.57 ; v2(4580.57,9057.57) J6.2@4638.44,9057.57 ; v2(4580.57,9115.44) J6.2@4638.44,9115.44 ; v2(4638.44,8939.63) J6.2@4638.44,8997.5 ; J6.2@4638.74,9000 v2@4678,9000 ; v2@4677.7,9057.57 J6.2@4638.44,9057.57 ; v2@4677.7,9115.44 J6.2@4638.44,9115.44 ; D5.2@4734.4,2062.98 v7(4808.79,2062.98) ; D3.2@4736.22,1983.98 v7(4810.61,1983.98) ; D4.2@4737.54,1909.24 v7(4811.93,1909.24) ; v2@4817,9000 4856.26,9000 J6.3@4856.56,8999.7 ; v2@4817.3,9057.57 J6.3@4856.56,9057.57 ; v2@4817.3,9115.44 J6.3@4856.56,9115.44 ; v2(4856.56,8939.63) J6.3@4856.56,8997.5 ; v2(4914.43,8999.7) J6.3@4856.56,8999.7 ; v2(4914.43,9057.57) J6.3@4856.56,9057.57 ; v2(4914.43,9115.44) J6.3@4856.56,9115.44 ; v3(4947.5,5061.5) C6.1@4947.5,5104 ; v3(4947.5,5146.5) C6.1@4947.5,5104 ; v3(4990,5104) C6.1@4947.5,5104 ; v3@5017.76,1338.08 C21.1@5017.76,1369.18 ; v2(5080.57,8999.7) 5138.44,8999.7 J7.2@5138.44,9057.57 ; v2(5080.57,9057.57) J7.2@5138.44,9057.57 ; v2(5080.57,9115.44) J7.2@5138.44,9115.44 ; v2(5138.44,8939.63) J7.2@5138.44,8997.5 ; J7.2@5138.74,9000 v2@5178,9000 ; v2@5177.7,9057.57 J7.2@5138.44,9057.57 ; v2@5177.7,9115.44 J7.2@5138.44,9115.44 ; v2@5317,9000 5356.26,9000 J7.3@5356.56,8999.7 ; v2@5317.3,9057.57 J7.3@5356.56,9057.57 ; v2@5317.3,9115.44 J7.3@5356.56,9115.44 ; v2(5356.56,8939.63) J7.3@5356.56,8997.5 ; v2(5414.43,8999.7) J7.3@5356.56,8999.7 ; v2(5414.43,9057.57) J7.3@5356.56,9057.57 ; v2(5414.43,9115.44) J7.3@5356.56,9115.44 ; v2(5580.57,8999.7) 5638.44,8999.7 J5.2@5638.44,9057.57 ; v2(5580.57,9057.57) J5.2@5638.44,9057.57 ; v2(5580.57,9115.44) J5.2@5638.44,9115.44 ; v2(5638.44,8939.63) J5.2@5638.44,8997.5 ; J5.2@5638.74,9000 v2@5678,9000 ; v8(5673.9,1327) v8@5673.9,1329.2 ; v2@5677.7,9057.57 J5.2@5638.44,9057.57 ; v2@5677.7,9115.44 J5.2@5638.44,9115.44 ; v3(5804.66,783.72) D1.2@5866.47,783.72 D1.2@5866.47,785 ; v2@5817,9000 5856.26,9000 J5.3@5856.56,8999.7 ; v2@5817.3,9057.57 J5.3@5856.56,9057.57 ; v2@5817.3,9115.44 J5.3@5856.56,9115.44 ; v2(5856.56,8939.63) J5.3@5856.56,8997.5 ; D1.2@5866,785 D1.2@5866.47,785 ; v3(5866.47,845.53) D1.2@5866.47,785 ; v2(5914.43,8999.7) J5.3@5856.56,8999.7 ; v2(5914.43,9057.57) J5.3@5856.56,9057.57 ; v2(5914.43,9115.44) J5.3@5856.56,9115.44 ; v3(5927.81,785) D1.2@5866.47,785 ; v3(6029.53,288.86) D2.2@6091.34,288.86 ; v2(6080.57,8999.7) 6138.44,8999.7 J4.2@6138.44,9057.57 ; v2(6080.57,9057.57) J4.2@6138.44,9057.57 ; v2(6080.57,9115.44) J4.2@6138.44,9115.44 ; v3(6091.34,227.05) D2.2@6091.34,288.86 ; v2(6138.44,8939.63) J4.2@6138.44,8997.5 ; J4.2@6138.74,9000 v2@6178,9000 ; v3(6153.15,288.86) D2.2@6091.34,288.86 ; v2@6177.7,9057.57 J4.2@6138.44,9057.57 ; v2@6177.7,9115.44 J4.2@6138.44,9115.44 ; v2@6317,9000 6356.26,9000 J4.3@6356.56,8999.7 ; v2@6317.3,9057.57 J4.3@6356.56,9057.57 ; v2@6317.3,9115.44 J4.3@6356.56,9115.44 ; v2(6356.56,8939.63) J4.3@6356.56,8997.5 ; v2(6414.43,8999.7) J4.3@6356.56,8999.7 ; v2(6414.43,9057.57) J4.3@6356.56,9057.57 ; v2(6414.43,9115.44) J4.3@6356.56,9115.44 ; v2(6777.83,2503.44) J13.3@6838.7,2503.44 ; v2(6777.83,2721.56) J13.2@6838.7,2721.56 ; v2(6777.83,3003.44) J15.3@6838.7,3003.44 ; v2(6777.83,3221.56) J15.2@6838.7,3221.56 ; v2(6777.83,3503.44) J16.3@6838.7,3503.44 ; v2(6777.83,3721.56) J16.2@6838.7,3721.56 ; v2(6777.83,4003.44) J14.3@6838.7,4003.44 ; v2(6777.83,4221.56) J14.2@6838.7,4221.56 ; v2(6777.83,4503.44) J18.3@6838.7,4503.44 ; v2(6777.83,4721.56) J18.2@6838.7,4721.56 ; v2(6777.83,5003.44) J20.3@6838.7,5003.44 ; v2(6777.83,5221.56) J20.2@6838.7,5221.56 ; v2(6777.83,5503.44) J19.3@6838.7,5503.44 ; v2(6777.83,5721.56) J19.2@6838.7,5721.56 ; v2(6777.83,6003.44) J17.3@6838.7,6003.44 ; v2(6777.83,6221.56) J17.2@6838.7,6221.56 ; v2(6777.83,6503.44) J21.3@6838.7,6503.44 ; v2(6777.83,6721.56) J21.2@6838.7,6721.56 ; v2(6777.83,7003.44) J23.3@6838.7,7003.44 ; v2(6777.83,7221.56) J23.2@6838.7,7221.56 ; v2(6777.83,7503.44) J24.3@6838.7,7503.44 ; v2(6777.83,7721.56) J24.2@6838.7,7721.56 ; v2(6777.83,8003.44) J22.3@6838.7,8003.44 ; v2(6777.83,8221.56) J22.2@6838.7,8221.56 ; v2(6778.63,770.94) J3.3@6836.5,770.94 ; v2(6778.63,989.06) J3.2@6836.5,989.06 ; v2(6778.63,1380.94) J2.3@6836.5,1380.94 ; v2(6778.63,1599.06) J2.2@6836.5,1599.06 ; v2(6838.7,713.07) 6838.7,770.94 J3.3@6896.57,770.94 ; v2(6838.7,1046.93) 6838.7,989.06 J3.2@6896.57,989.06 ; v2(6838.7,1323.07) 6838.7,1380.94 J2.3@6896.57,1380.94 ; v2(6838.7,1656.93) 6838.7,1599.06 J2.2@6896.57,1599.06 ; v2(6838.7,2445.57) J13.3@6838.7,2503.44 ; v2(6838.7,2779.43) J13.2@6838.7,2721.56 ; v2(6838.7,2945.57) J15.3@6838.7,3003.44 ; v2(6838.7,3279.43) J15.2@6838.7,3221.56 ; v2(6838.7,3445.57) J16.3@6838.7,3503.44 ; v2(6838.7,3779.43) J16.2@6838.7,3721.56 ; v2(6838.7,3945.57) J14.3@6838.7,4003.44 ; v2(6838.7,4279.43) J14.2@6838.7,4221.56 ; v2(6838.7,4445.57) J18.3@6838.7,4503.44 ; v2(6838.7,4779.43) J18.2@6838.7,4721.56 ; v2(6838.7,4945.57) J20.3@6838.7,5003.44 ; v2(6838.7,5279.43) J20.2@6838.7,5221.56 ; v2(6838.7,5445.57) J19.3@6838.7,5503.44 ; v2(6838.7,5779.43) J19.2@6838.7,5721.56 ; v2(6838.7,5945.57) J17.3@6838.7,6003.44 ; v2(6838.7,6279.43) J17.2@6838.7,6221.56 ; v2(6838.7,6445.57) J21.3@6838.7,6503.44 ; v2(6838.7,6779.43) J21.2@6838.7,6721.56 ; v2(6838.7,6945.57) J23.3@6838.7,7003.44 ; v2(6838.7,7279.43) J23.2@6838.7,7221.56 ; v2(6838.7,7445.57) J24.3@6838.7,7503.44 ; v2(6838.7,7779.43) J24.2@6838.7,7721.56 ; v2(6838.7,7945.57) J22.3@6838.7,8003.44 ; v2(6838.7,8279.43) J22.2@6838.7,8221.56 ; v2@6839,2543 6839,2503.74 J13.3@6838.7,2503.44 ; v2@6839,2682 6839,2721.26 J13.2@6838.7,2721.56 ; v2@6839,3043 6839,3003.74 J15.3@6838.7,3003.44 ; v2@6839,3182 6839,3221.26 J15.2@6838.7,3221.56 ; v2@6839,3543 6839,3503.74 J16.3@6838.7,3503.44 ; v2@6839,3682 6839,3721.26 J16.2@6838.7,3721.56 ; v2@6839,4043 6839,4003.74 J14.3@6838.7,4003.44 ; v2@6839,4182 6839,4221.26 J14.2@6838.7,4221.56 ; v2@6839,4543 6839,4503.74 J18.3@6838.7,4503.44 ; v2@6839,4682 6839,4721.26 J18.2@6838.7,4721.56 ; v2@6839,5043 6839,5003.74 J20.3@6838.7,5003.44 ; v2@6839,5182 6839,5221.26 J20.2@6838.7,5221.56 ; v2@6839,5543 6839,5503.74 J19.3@6838.7,5503.44 ; v2@6839,5682 6839,5721.26 J19.2@6838.7,5721.56 ; v2@6839,6043 6839,6003.74 J17.3@6838.7,6003.44 ; v2@6839,6182 6839,6221.26 J17.2@6838.7,6221.56 ; v2@6839,6543 6839,6503.74 J21.3@6838.7,6503.44 ; v2@6839,6682 6839,6721.26 J21.2@6838.7,6721.56 ; v2@6839,7043 6839,7003.74 J23.3@6838.7,7003.44 ; v2@6839,7182 6839,7221.26 J23.2@6838.7,7221.56 ; v2@6839,7543 6839,7503.74 J24.3@6838.7,7503.44 ; v2@6839,7682 6839,7721.26 J24.2@6838.7,7721.56 ; v2@6839,8043 6839,8003.74 J22.3@6838.7,8003.44 ; v2@6839,8182 6839,8221.26 J22.2@6838.7,8221.56 ; v2(6896.57,713.07) J3.3@6896.57,770.94 ; v2(6896.57,1046.93) J3.2@6896.57,989.06 ; v2(6896.57,1323.07) J2.3@6896.57,1380.94 ; v2(6896.57,1656.93) J2.2@6896.57,1599.06 ; v2(6896.57,2445.57) J13.3@6896.57,2503.44 ; v2@6896.57,2542.7 J13.3@6896.57,2503.44 ; v2@6896.57,2682.3 J13.2@6896.57,2721.56 ; v2(6896.57,2779.43) J13.2@6896.57,2721.56 ; v2(6896.57,2945.57) J15.3@6896.57,3003.44 ; v2@6896.57,3042.7 J15.3@6896.57,3003.44 ; v2@6896.57,3182.3 J15.2@6896.57,3221.56 ; v2(6896.57,3279.43) J15.2@6896.57,3221.56 ; v2(6896.57,3445.57) J16.3@6896.57,3503.44 ; v2@6896.57,3542.7 J16.3@6896.57,3503.44 ; v2@6896.57,3682.3 J16.2@6896.57,3721.56 ; v2(6896.57,3779.43) J16.2@6896.57,3721.56 ; v2(6896.57,3945.57) J14.3@6896.57,4003.44 ; v2@6896.57,4042.7 J14.3@6896.57,4003.44 ; v2@6896.57,4182.3 J14.2@6896.57,4221.56 ; v2(6896.57,4279.43) J14.2@6896.57,4221.56 ; v2(6896.57,4445.57) J18.3@6896.57,4503.44 ; v2@6896.57,4542.7 J18.3@6896.57,4503.44 ; v2@6896.57,4682.3 J18.2@6896.57,4721.56 ; v2(6896.57,4779.43) J18.2@6896.57,4721.56 ; v2(6896.57,4945.57) J20.3@6896.57,5003.44 ; v2@6896.57,5042.7 J20.3@6896.57,5003.44 ; v2@6896.57,5182.3 J20.2@6896.57,5221.56 ; v2(6896.57,5279.43) J20.2@6896.57,5221.56 ; v2(6896.57,5445.57) J19.3@6896.57,5503.44 ; v2@6896.57,5542.7 J19.3@6896.57,5503.44 ; v2@6896.57,5682.3 J19.2@6896.57,5721.56 ; v2(6896.57,5779.43) J19.2@6896.57,5721.56 ; v2(6896.57,5945.57) J17.3@6896.57,6003.44 ; v2@6896.57,6042.7 J17.3@6896.57,6003.44 ; v2@6896.57,6182.3 J17.2@6896.57,6221.56 ; v2(6896.57,6279.43) J17.2@6896.57,6221.56 ; v2(6896.57,6445.57) J21.3@6896.57,6503.44 ; v2@6896.57,6542.7 J21.3@6896.57,6503.44 ; v2@6896.57,6682.3 J21.2@6896.57,6721.56 ; v2(6896.57,6779.43) J21.2@6896.57,6721.56 ; v2(6896.57,6945.57) J23.3@6896.57,7003.44 ; v2@6896.57,7042.7 J23.3@6896.57,7003.44 ; v2@6896.57,7182.3 J23.2@6896.57,7221.56 ; v2(6896.57,7279.43) J23.2@6896.57,7221.56 ; v2(6896.57,7445.57) J24.3@6896.57,7503.44 ; v2@6896.57,7542.7 J24.3@6896.57,7503.44 ; v2@6896.57,7682.3 J24.2@6896.57,7721.56 ; v2(6896.57,7779.43) J24.2@6896.57,7721.56 ; v2(6896.57,7945.57) J22.3@6896.57,8003.44 ; v2@6896.57,8042.7 J22.3@6896.57,8003.44 ; v2@6896.57,8182.3 J22.2@6896.57,8221.56 ; v2(6896.57,8279.43) J22.2@6896.57,8221.56 ; v2(6954.44,713.07) 6954.44,770.94 J3.3@6896.57,770.94 ; v2(6954.44,1046.93) 6954.44,989.06 J3.2@6896.57,989.06 ; v2(6954.44,1323.07) 6954.44,1380.94 J2.3@6896.57,1380.94 ; v2(6954.44,1656.93) 6954.44,1599.06 J2.2@6896.57,1599.06 ; v2(6954.44,2445.57) J13.3@6954.44,2503.44 ; v2@6954.44,2542.7 J13.3@6954.44,2503.44 ; v2@6954.44,2682.3 J13.2@6954.44,2721.56 ; v2(6954.44,2779.43) J13.2@6954.44,2721.56 ; v2(6954.44,2945.57) J15.3@6954.44,3003.44 ; v2@6954.44,3042.7 J15.3@6954.44,3003.44 ; v2@6954.44,3182.3 J15.2@6954.44,3221.56 ; v2(6954.44,3279.43) J15.2@6954.44,3221.56 ; v2(6954.44,3445.57) J16.3@6954.44,3503.44 ; v2@6954.44,3542.7 J16.3@6954.44,3503.44 ; v2@6954.44,3682.3 J16.2@6954.44,3721.56 ; v2(6954.44,3779.43) J16.2@6954.44,3721.56 ; v2(6954.44,3945.57) J14.3@6954.44,4003.44 ; v2@6954.44,4042.7 J14.3@6954.44,4003.44 ; v2@6954.44,4182.3 J14.2@6954.44,4221.56 ; v2(6954.44,4279.43) J14.2@6954.44,4221.56 ; v2(6954.44,4445.57) J18.3@6954.44,4503.44 ; v2@6954.44,4542.7 J18.3@6954.44,4503.44 ; v2@6954.44,4682.3 J18.2@6954.44,4721.56 ; v2(6954.44,4779.43) J18.2@6954.44,4721.56 ; v2(6954.44,4945.57) J20.3@6954.44,5003.44 ; v2@6954.44,5042.7 J20.3@6954.44,5003.44 ; v2@6954.44,5182.3 J20.2@6954.44,5221.56 ; v2(6954.44,5279.43) J20.2@6954.44,5221.56 ; v2(6954.44,5445.57) J19.3@6954.44,5503.44 ; v2@6954.44,5542.7 J19.3@6954.44,5503.44 ; v2@6954.44,5682.3 J19.2@6954.44,5721.56 ; v2(6954.44,5779.43) J19.2@6954.44,5721.56 ; v2(6954.44,5945.57) J17.3@6954.44,6003.44 ; v2@6954.44,6042.7 J17.3@6954.44,6003.44 ; v2@6954.44,6182.3 J17.2@6954.44,6221.56 ; v2(6954.44,6279.43) J17.2@6954.44,6221.56 ; v2(6954.44,6445.57) J21.3@6954.44,6503.44 ; v2@6954.44,6542.7 J21.3@6954.44,6503.44 ; v2@6954.44,6682.3 J21.2@6954.44,6721.56 ; v2(6954.44,6779.43) J21.2@6954.44,6721.56 ; v2(6954.44,6945.57) J23.3@6954.44,7003.44 ; v2@6954.44,7042.7 J23.3@6954.44,7003.44 ; v2@6954.44,7182.3 J23.2@6954.44,7221.56 ; v2(6954.44,7279.43) J23.2@6954.44,7221.56 ; v2(6954.44,7445.57) J24.3@6954.44,7503.44 ; v2@6954.44,7542.7 J24.3@6954.44,7503.44 ; v2@6954.44,7682.3 J24.2@6954.44,7721.56 ; v2(6954.44,7779.43) J24.2@6954.44,7721.56 ; v2(6954.44,7945.57) J22.3@6954.44,8003.44 ; v2@6954.44,8042.7 J22.3@6954.44,8003.44 ; v2@6954.44,8182.3 J22.2@6954.44,8221.56 ; v2(6954.44,8279.43) J22.2@6954.44,8221.56 ; J10.2@45.56,2503.44 J10.2@103.43,2503.44 ; J10.3@45.56,2721.56 J10.3@103.43,2721.56 ; J12.2@45.56,3003.44 J12.2@103.43,3003.44 ; J12.3@45.56,3221.56 J12.3@103.43,3221.56 ; J11.2@45.56,3503.44 J11.2@103.43,3503.44 ; J11.3@45.56,3721.56 J11.3@103.43,3721.56 ; J9.2@45.56,4003.44 J9.2@103.43,4003.44 ; J9.3@45.56,4221.56 J9.3@103.43,4221.56 ; J34.2@45.56,4503.44 J34.2@103.43,4503.44 ; J34.3@45.56,4721.56 J34.3@103.43,4721.56 ; J36.2@45.56,5003.44 J36.2@103.43,5003.44 ; J36.3@45.56,5221.56 J36.3@103.43,5221.56 ; J35.2@45.56,5503.44 J35.2@103.43,5503.44 ; J35.3@45.56,5721.56 J35.3@103.43,5721.56 ; J33.2@45.56,6003.44 J33.2@103.43,6003.44 ; J33.3@45.56,6221.56 J33.3@103.43,6221.56 ; J30.2@45.56,6503.44 J30.2@103.43,6503.44 ; J30.3@45.56,6721.56 J30.3@103.43,6721.56 ; J32.2@45.56,7003.44 J32.2@103.43,7003.44 ; J32.3@45.56,7221.56 J32.3@103.43,7221.56 ; J31.2@45.56,7503.44 J31.2@103.43,7503.44 ; J31.3@45.56,7721.56 J31.3@103.43,7721.56 ; J29.2@45.56,8003.44 J29.2@103.43,8003.44 ; J29.3@45.56,8221.56 J29.3@103.43,8221.56 ; J10.2@103.43,2503.44 J10.2@161.3,2503.44 ; J10.3@103.43,2721.56 J10.3@161.3,2721.56 ; J12.2@103.43,3003.44 J12.2@161.3,3003.44 ; J12.3@103.43,3221.56 J12.3@161.3,3221.56 ; J11.2@103.43,3503.44 J11.2@161.3,3503.44 ; J11.3@103.43,3721.56 J11.3@161.3,3721.56 ; J9.2@103.43,4003.44 J9.2@161.3,4003.44 ; J9.3@103.43,4221.56 J9.3@161.3,4221.56 ; J34.2@103.43,4503.44 J34.2@161.3,4503.44 ; J34.3@103.43,4721.56 J34.3@161.3,4721.56 ; J36.2@103.43,5003.44 J36.2@161.3,5003.44 ; J36.3@103.43,5221.56 J36.3@161.3,5221.56 ; J35.2@103.43,5503.44 J35.2@161.3,5503.44 ; J35.3@103.43,5721.56 J35.3@161.3,5721.56 ; J33.2@103.43,6003.44 J33.2@161.3,6003.44 ; J33.3@103.43,6221.56 J33.3@161.3,6221.56 ; J30.2@103.43,6503.44 J30.2@161.3,6503.44 ; J30.3@103.43,6721.56 J30.3@161.3,6721.56 ; J32.2@103.43,7003.44 J32.2@161.3,7003.44 ; J32.3@103.43,7221.56 J32.3@161.3,7221.56 ; J31.2@103.43,7503.44 J31.2@161.3,7503.44 ; J31.3@103.43,7721.56 J31.3@161.3,7721.56 ; J29.2@103.43,8003.44 J29.2@161.3,8003.44 ; J29.3@103.43,8221.56 J29.3@161.3,8221.56 ; J26.2@638.44,8999.7 J26.2@638.44,9057.57 ; J26.2@638.44,9057.57 J26.2@638.44,9115.44 ; J26.3@856.56,8999.7 J26.3@856.56,9057.57 ; J26.3@856.56,9057.57 J26.3@856.56,9115.44 ; J28.2@1138.44,8999.7 J28.2@1138.44,9057.57 ; J28.2@1138.44,9057.57 J28.2@1138.44,9115.44 ; J28.3@1356.56,8999.7 J28.3@1356.56,9057.57 ; J28.3@1356.56,9057.57 J28.3@1356.56,9115.44 ; J27.2@1638.44,8999.7 J27.2@1638.44,9057.57 ; J27.2@1638.44,9057.57 J27.2@1638.44,9115.44 ; J27.3@1856.56,8999.7 J27.3@1856.56,9057.57 ; J27.3@1856.56,9057.57 J27.3@1856.56,9115.44 ; J25.2@2138.44,9057.57 J25.2@2138.44,9115.44 ; J25.3@2356.56,8999.7 J25.3@2356.56,9057.57 ; J25.3@2356.56,9057.57 J25.3@2356.56,9115.44 ; J38.2@2638.44,9057.57 J38.2@2638.44,9115.44 ; J38.3@2856.56,8999.7 J38.3@2856.56,9057.57 ; J38.3@2856.56,9057.57 J38.3@2856.56,9115.44 ; J40.2@3138.44,9057.57 J40.2@3138.44,9115.44 ; J40.3@3356.56,8999.7 J40.3@3356.56,9057.57 ; J40.3@3356.56,9057.57 J40.3@3356.56,9115.44 ; J39.2@3638.44,9057.57 J39.2@3638.44,9115.44 ; J39.3@3856.56,8999.7 J39.3@3856.56,9057.57 ; J39.3@3856.56,9057.57 J39.3@3856.56,9115.44 ; J37.2@4138.44,9057.57 J37.2@4138.44,9115.44 ; J37.3@4356.56,8999.7 J37.3@4356.56,9057.57 ; J37.3@4356.56,9057.57 J37.3@4356.56,9115.44 ; J6.2@4638.44,9057.57 J6.2@4638.44,9115.44 ; J6.3@4856.56,8999.7 J6.3@4856.56,9057.57 ; J6.3@4856.56,9057.57 J6.3@4856.56,9115.44 ; J7.2@5138.44,9057.57 J7.2@5138.44,9115.44 ; J7.3@5356.56,8999.7 J7.3@5356.56,9057.57 ; J7.3@5356.56,9057.57 J7.3@5356.56,9115.44 ; J5.2@5638.44,9057.57 J5.2@5638.44,9115.44 ; J5.3@5856.56,8999.7 J5.3@5856.56,9057.57 ; J5.3@5856.56,9057.57 J5.3@5856.56,9115.44 ; J4.2@6138.44,9057.57 J4.2@6138.44,9115.44 ; J4.3@6356.56,8999.7 J4.3@6356.56,9057.57 ; J4.3@6356.56,9057.57 J4.3@6356.56,9115.44 ; J13.3@6838.7,2503.44 J13.3@6896.57,2503.44 ; J13.2@6838.7,2721.56 J13.2@6896.57,2721.56 ; J15.3@6838.7,3003.44 J15.3@6896.57,3003.44 ; J15.2@6838.7,3221.56 J15.2@6896.57,3221.56 ; J16.3@6838.7,3503.44 J16.3@6896.57,3503.44 ; J16.2@6838.7,3721.56 J16.2@6896.57,3721.56 ; J14.3@6838.7,4003.44 J14.3@6896.57,4003.44 ; J14.2@6838.7,4221.56 J14.2@6896.57,4221.56 ; J18.3@6838.7,4503.44 J18.3@6896.57,4503.44 ; J18.2@6838.7,4721.56 J18.2@6896.57,4721.56 ; J20.3@6838.7,5003.44 J20.3@6896.57,5003.44 ; J20.2@6838.7,5221.56 J20.2@6896.57,5221.56 ; J19.3@6838.7,5503.44 J19.3@6896.57,5503.44 ; J19.2@6838.7,5721.56 J19.2@6896.57,5721.56 ; J17.3@6838.7,6003.44 J17.3@6896.57,6003.44 ; J17.2@6838.7,6221.56 J17.2@6896.57,6221.56 ; J21.3@6838.7,6503.44 J21.3@6896.57,6503.44 ; J21.2@6838.7,6721.56 J21.2@6896.57,6721.56 ; J23.3@6838.7,7003.44 J23.3@6896.57,7003.44 ; J23.2@6838.7,7221.56 J23.2@6896.57,7221.56 ; J24.3@6838.7,7503.44 J24.3@6896.57,7503.44 ; J24.2@6838.7,7721.56 J24.2@6896.57,7721.56 ; J22.3@6838.7,8003.44 J22.3@6896.57,8003.44 ; J22.2@6838.7,8221.56 J22.2@6896.57,8221.56 ; J13.3@6896.57,2503.44 J13.3@6954.44,2503.44 ; J13.2@6896.57,2721.56 J13.2@6954.44,2721.56 ; J15.3@6896.57,3003.44 J15.3@6954.44,3003.44 ; J15.2@6896.57,3221.56 J15.2@6954.44,3221.56 ; J16.3@6896.57,3503.44 J16.3@6954.44,3503.44 ; J16.2@6896.57,3721.56 J16.2@6954.44,3721.56 ; J14.3@6896.57,4003.44 J14.3@6954.44,4003.44 ; J14.2@6896.57,4221.56 J14.2@6954.44,4221.56 ; J18.3@6896.57,4503.44 J18.3@6954.44,4503.44 ; J18.2@6896.57,4721.56 J18.2@6954.44,4721.56 ; J20.3@6896.57,5003.44 J20.3@6954.44,5003.44 ; J20.2@6896.57,5221.56 J20.2@6954.44,5221.56 ; J19.3@6896.57,5503.44 J19.3@6954.44,5503.44 ; J19.2@6896.57,5721.56 J19.2@6954.44,5721.56 ; J17.3@6896.57,6003.44 J17.3@6954.44,6003.44 ; J17.2@6896.57,6221.56 J17.2@6954.44,6221.56 ; J21.3@6896.57,6503.44 J21.3@6954.44,6503.44 ; J21.2@6896.57,6721.56 J21.2@6954.44,6721.56 ; J23.3@6896.57,7003.44 J23.3@6954.44,7003.44 ; J23.2@6896.57,7221.56 J23.2@6954.44,7221.56 ; J24.3@6896.57,7503.44 J24.3@6954.44,7503.44 ; J24.2@6896.57,7721.56 J24.2@6954.44,7721.56 ; J22.3@6896.57,8003.44 J22.3@6954.44,8003.44 ; J22.2@6896.57,8221.56 J22.2@6954.44,8221.56
  L1-Top Layer (GTL) w25: v3(4423.76,2992.57) C78.2@4423.76,3032.57
  L1-Top Layer (GTL) w30: v8(5114.2,2095.3) C516.2@5114.2,2156.28 ; v8(5289.4,2082.4) C515.2@5289.4,2143.2 ; v7(5394.02,1336.34) C27.2@5448.12,1336.34 v3(5448.12,1284.22) ; v8@5477.88,821.78 C504.2@5543.6,821.78 ; v8(5673.9,1327) C514.2@5673.9,1389.48 ; C513.2@5740.8,1378.6 5740.8,1324.8 v8(5817,1324.8) ; v3(5953.08,718.49) C10.2@6005.2,718.49 ; v3(6005.2,770.61) C10.2@6005.2,718.49 ; v3(6057.32,718.49) C10.2@6005.2,718.49 ; v8(6150.2,996.3) C500.2@6228.51,995.9 ; C510.2@6188.03,1130 v8(6241.6,1130) ; C509.2@6188.03,1202.9 v8(6240.9,1202.9) ; C508.2@6188.03,1276.1 v8(6241.2,1276.1)
  L1-Top Layer (GTL) w35: R502.1@6579.5,1680.8 v5(6623.9,1680.8)
  L1-Top Layer (GTL) w40: J500.5@5857.7,101.2 v8(5917.9,161.4)
  L3-Mid-Layer 2 (G1) w20: v1(3687.09,6066.46) 3697.6,6076.97 v1(3697.6,6098.64) ; 5097.28,3518.08 v1(5128.91,3518.08)
  L3-Mid-Layer 2 (G1) w30: 780.5,8723.67 ccw(c747.5,8723.67) 780.5,8723.67 ; v5@1280.5,8723.67 ccw(c1247.5,8723.67) v5@1280.5,8723.67 ; 1780.5,8723.67 ccw(c1747.5,8723.67) 1780.5,8723.67 ; v5@2280.5,8723.67 ccw(c2247.5,8723.67) v5@2280.5,8723.67 ; 2780.5,8723.67 ccw(c2747.5,8723.67) 2780.5,8723.67 ; 2861.3,5677.02 ccw(c2884.64,5653.69) 2907.97,5630.35 2939.08,5661.47 ccw(c2915.75,5684.8) 2892.42,5708.13 2861.3,5677.02 ; 2977.46,5731.87 ccw(c3000.79,5708.54) 3024.12,5685.21 3055.24,5716.32 ccw(c3031.9,5739.65) 3008.57,5762.99 2977.46,5731.87 ; v5@3280.5,8723.67 ccw(c3247.5,8723.67) v5@3280.5,8723.67 ; 3284.39,5782.49 cw(c3284.39,5815.49) 3284.39,5848.49 3328.39,5848.49 cw(c3328.39,5815.49) 3328.39,5782.49 3284.39,5782.49 ; 3400.59,5894.67 cw(c3400.59,5927.67) 3400.59,5960.67 3444.59,5960.67 cw(c3444.59,5927.67) 3444.59,5894.67 3400.59,5894.67 ; 3780.5,8723.67 ccw(c3747.5,8723.67) 3780.5,8723.67 ; 3869.84,5464.22 ccw(c3902.84,5464.22) 3935.84,5464.22 3935.84,5508.22 ccw(c3902.84,5508.22) 3869.84,5508.22 3869.84,5464.22 ; 3965.89,5309.45 ccw(c3998.89,5309.45) 4031.89,5309.45 4031.89,5353.45 ccw(c3998.89,5353.45) 3965.89,5353.45 3965.89,5309.45 ; v5@4280.5,8723.67 ccw(c4247.5,8723.67) v5@4280.5,8723.67 ; 6593.67,4612.5 ccw(c6560.67,4612.5) 6593.67,4612.5 ; 6593.67,5112.5 ccw(c6560.67,5112.5) 6593.67,5112.5 ; 6593.67,5612.5 ccw(c6560.67,5612.5) 6593.67,5612.5 ; 6593.67,6112.5 ccw(c6560.67,6112.5) 6593.67,6112.5
  L4-Mid-Layer 3 (G2) w30: 780.5,8723.67 ccw(c747.5,8723.67) 780.5,8723.67 ; v5@1280.5,8723.67 ccw(c1247.5,8723.67) v5@1280.5,8723.67 ; 1780.5,8723.67 ccw(c1747.5,8723.67) 1780.5,8723.67 ; v5@2280.5,8723.67 ccw(c2247.5,8723.67) v5@2280.5,8723.67 ; 2780.5,8723.67 ccw(c2747.5,8723.67) 2780.5,8723.67 ; 2861.3,5677.02 ccw(c2884.64,5653.69) 2907.97,5630.35 2939.08,5661.46 ccw(c2915.75,5684.8) 2892.42,5708.13 2861.3,5677.02 ; 2977.45,5731.87 ccw(c3000.79,5708.54) 3024.12,5685.2 3055.24,5716.32 ccw(c3031.9,5739.65) 3008.57,5762.99 2977.45,5731.87 ; v5@3280.5,8723.67 ccw(c3247.5,8723.67) v5@3280.5,8723.67 ; 3284.39,5782.49 cw(c3284.39,5815.49) 3284.39,5848.49 3328.39,5848.49 cw(c3328.39,5815.49) 3328.39,5782.49 3284.39,5782.49 ; 3400.59,5894.67 cw(c3400.59,5927.67) 3400.59,5960.67 3444.59,5960.67 cw(c3444.59,5927.67) 3444.59,5894.67 3400.59,5894.67 ; 3780.5,8723.67 ccw(c3747.5,8723.67) 3780.5,8723.67 ; 3869.84,5464.22 ccw(c3902.84,5464.22) 3935.84,5464.22 3935.84,5508.22 ccw(c3902.84,5508.22) 3869.84,5508.22 3869.84,5464.22 ; 3965.89,5309.45 ccw(c3998.89,5309.45) 4031.89,5309.45 4031.89,5353.45 ccw(c3998.89,5353.45) 3965.89,5353.45 3965.89,5309.45 ; v5@4280.5,8723.67 ccw(c4247.5,8723.67) v5@4280.5,8723.67 ; 6593.67,4612.5 ccw(c6560.67,4612.5) 6593.67,4612.5 ; 6593.67,5112.5 ccw(c6560.67,5112.5) 6593.67,5112.5 ; 6593.67,5612.5 ccw(c6560.67,5612.5) 6593.67,5612.5 ; 6593.67,6112.5 ccw(c6560.67,6112.5) 6593.67,6112.5
  L5-Mid-Layer 4 (G3) w30: 780.5,8723.67 ccw(c747.5,8723.67) 780.5,8723.67 ; v5@1280.5,8723.67 ccw(c1247.5,8723.67) v5@1280.5,8723.67 ; 1780.5,8723.67 ccw(c1747.5,8723.67) 1780.5,8723.67 ; v5@2280.5,8723.67 ccw(c2247.5,8723.67) v5@2280.5,8723.67 ; 2780.5,8723.67 ccw(c2747.5,8723.67) 2780.5,8723.67 ; 2861.3,5677.02 ccw(c2884.64,5653.69) 2907.97,5630.35 2939.08,5661.47 ccw(c2915.75,5684.8) 2892.42,5708.13 2861.3,5677.02 ; 2977.46,5731.87 ccw(c3000.79,5708.54) 3024.12,5685.21 3055.24,5716.32 ccw(c3031.9,5739.65) 3008.57,5762.99 2977.46,5731.87 ; v5@3280.5,8723.67 ccw(c3247.5,8723.67) v5@3280.5,8723.67 ; 3284.39,5782.49 cw(c3284.39,5815.49) 3284.39,5848.49 3328.39,5848.49 cw(c3328.39,5815.49) 3328.39,5782.49 3284.39,5782.49 ; 3400.59,5894.67 cw(c3400.59,5927.67) 3400.59,5960.67 3444.59,5960.67 cw(c3444.59,5927.67) 3444.59,5894.67 3400.59,5894.67 ; 3780.5,8723.67 ccw(c3747.5,8723.67) 3780.5,8723.67 ; 3869.84,5464.22 ccw(c3902.84,5464.22) 3935.84,5464.22 3935.84,5508.22 ccw(c3902.84,5508.22) 3869.84,5508.22 3869.84,5464.22 ; 3965.89,5309.45 ccw(c3998.89,5309.45) 4031.89,5309.45 4031.89,5353.45 ccw(c3998.89,5353.45) 3965.89,5353.45 3965.89,5309.45 ; v5@4280.5,8723.67 ccw(c4247.5,8723.67) v5@4280.5,8723.67 ; 6593.67,4612.5 ccw(c6560.67,4612.5) 6593.67,4612.5 ; 6593.67,5112.5 ccw(c6560.67,5112.5) 6593.67,5112.5 ; 6593.67,5612.5 ccw(c6560.67,5612.5) 6593.67,5612.5 ; 6593.67,6112.5 ccw(c6560.67,6112.5) 6593.67,6112.5
  L7-Mid-Layer 6 (G5) w30: 780.5,8723.67 ccw(c747.5,8723.67) 780.5,8723.67 ; v5@1280.5,8723.67 ccw(c1247.5,8723.67) v5@1280.5,8723.67 ; 1780.5,8723.67 ccw(c1747.5,8723.67) 1780.5,8723.67 ; v5@2280.5,8723.67 ccw(c2247.5,8723.67) v5@2280.5,8723.67 ; 2780.5,8723.67 ccw(c2747.5,8723.67) 2780.5,8723.67 ; 2861.3,5677.02 ccw(c2884.64,5653.69) 2907.97,5630.35 2939.08,5661.47 ccw(c2915.75,5684.8) 2892.42,5708.13 2861.3,5677.02 ; 2977.46,5731.87 ccw(c3000.79,5708.54) 3024.12,5685.21 3055.24,5716.32 ccw(c3031.9,5739.65) 3008.57,5762.99 2977.46,5731.87 ; v5@3280.5,8723.67 ccw(c3247.5,8723.67) v5@3280.5,8723.67 ; 3284.39,5782.49 cw(c3284.39,5815.49) 3284.39,5848.49 3328.39,5848.49 cw(c3328.39,5815.49) 3328.39,5782.49 3284.39,5782.49 ; 3400.59,5894.67 cw(c3400.59,5927.67) 3400.59,5960.67 3444.59,5960.67 cw(c3444.59,5927.67) 3444.59,5894.67 3400.59,5894.67 ; 3780.5,8723.67 ccw(c3747.5,8723.67) 3780.5,8723.67 ; 3869.84,5464.22 ccw(c3902.84,5464.22) 3935.84,5464.22 3935.84,5508.22 ccw(c3902.84,5508.22) 3869.84,5508.22 3869.84,5464.22 ; 3965.89,5309.45 ccw(c3998.89,5309.45) 4031.89,5309.45 4031.89,5353.45 ccw(c3998.89,5353.45) 3965.89,5353.45 3965.89,5309.45 ; v5@4280.5,8723.67 ccw(c4247.5,8723.67) v5@4280.5,8723.67 ; 6593.67,4612.5 ccw(c6560.67,4612.5) 6593.67,4612.5 ; 6593.67,5112.5 ccw(c6560.67,5112.5) 6593.67,5112.5 ; 6593.67,5612.5 ccw(c6560.67,5612.5) 6593.67,5612.5 ; 6593.67,6112.5 ccw(c6560.67,6112.5) 6593.67,6112.5
  L8-Bottom Layer (GBL) w10: v11(1011,1549) 1029,1567 J42.27@1029,1702.96 ; J42.28@1029,1973.04 v11(1029,2117) ; C97.2@1554.5,1418 v11(1607,1418) ; J42.8@2029,1973.04 2029,2101 v11(2009,2121) 2104,2121 2129,2096 J42.6@2129,1973.04 ; J42.4@2229,1973.04 2229,2089.63 2250.37,2111 2306,2111 v11(2339,2144) ; v1(3747.89,5352.18) v1@3748.01,5352.06 ; U9.7@5000.26,2784.28 5000.26,2727.24 R9.1@5058.5,2669 v3@5111.99,2669 ; U9.6@5149.87,2784.28 5149.87,2735.64 C156.2@5286,2599.5 v3@5339.5,2599.5 ; C24.2@5280,2839.5 v3(5280,2889) ; C7.2@5987.2,2263.9 v4@6043.36,2263.9 ; C7.2@5999.36,2253.9 C7.2@5999.54,2253.72 ; U10.7@6020.16,1960.6 6020.16,1931.44 6122.16,1931.44 6139.54,1914.06 v4(6139.54,1830.72) R2.1@6087.7,1830.4 ; U10.6@6020.16,2110.2 6020.16,2137.36 6066.16,2137.36 6066.16,2040.44 6103.74,2040.44 C154.2@6105.2,2041.9 ; R2.1@6071.2,1827.9 R2.1@6073.7,1830.4 ; C154.2@6105.46,2038.72 v4(6162.54,2038.72) ; v8(6276.4,1480.4) 6296.8,1500.8 6313.9,1500.8 6322.1,1509 v5(6322.1,1520.3) ; U11.7@6317.4,1882.19 6366.18,1833.4 6432.2,1833.4 6437.7,1827.9 R5.1@6437.7,1730.4 v3(6481.7,1730.4) ; v5(6322.1,1542.3) v5(6322.1,1565.3) ; U11.6@6467,1882.19 6501.2,1882.4 v4(6500.54,1784.72) 6570.2,1784.4 6634.2,1784.4 C13.2@6634.2,1831.9 ; 6580.2,1784.4 C155.2@6580.2,1830.9
  L8-Bottom Layer (GBL) w11: C77.2@3043.3,6034.29 v1(3089.17,5988.43) ; C76.1@3081.55,5925.14 v1(3114.99,5891.7) ; C68.1@3665.78,4976.1 3669.74,4972.14 v3(3711.52,4972.14) 3710.24,4970.86 C69.2@3710.24,4912.19 ; C69.2@3711.52,4903.75 C69.2@3725.65,4889.62 ; v3(4047.22,5102.07) C73.1@4081.26,5068.02 ; v3@4152.02,5082.02 C74.2@4184.62,5049.42
  L8-Bottom Layer (GBL) w15: v1@3687.09,6066.17 v1(3687.09,6066.46) ; v1@3783.31,5968.52 v1(3783.31,5968.81)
